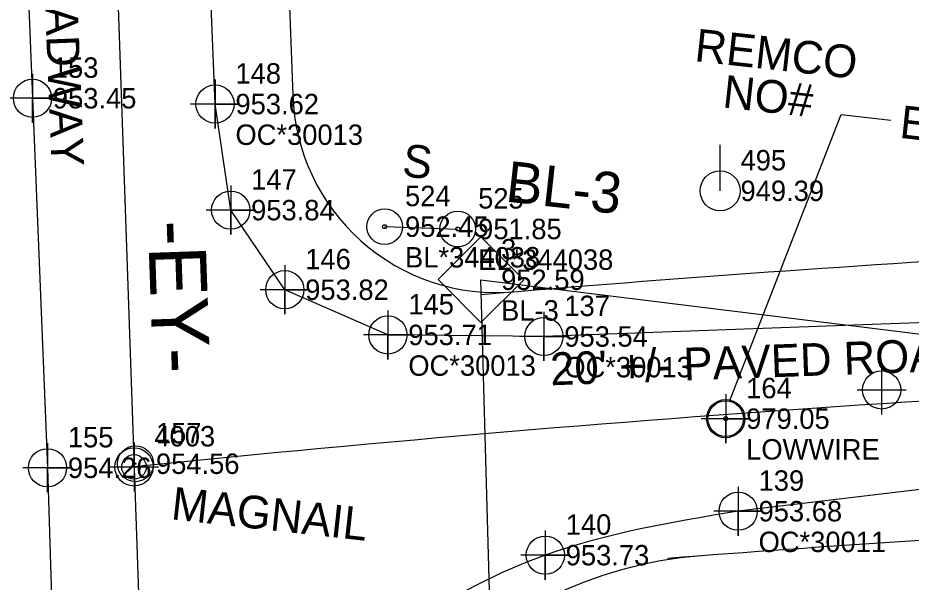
# Model space of a CAD drawing. Extents: x 1150279 to 1151282, y 655434 to 657999.
# Drawn here: x 1150558.1 to 1150667.5, y 657108.3 to 657177.3 of the extents above; entities that cross this region are included whole.
import ezdxf

# ---------------------------------------------------------------- set-up
doc = ezdxf.new("R2010")
doc.units = 0
for name, color, linetype in [('COGO Default Chain', 7, 'Continuous'), ('COGO Default Curve', 7, 'Continuous'), ('Cogo Default Point CELL', 7, 'Continuous'), ('COGO Default Point Number', 7, 'Continuous'), ('CTL Supplemental Horizontal and Vertical CELL', 7, 'Continuous'), ('CTL Supplemental Horizontal and Vertical Cogo Comment', 7, 'Continuous'), ('CTL Supplemental Horizontal and Vertical Cogo Elevation', 7, 'Continuous'), ('CTL Supplemental Horizontal and Vertical Cogo Number', 7, 'Continuous'), ('CTL Supplemental Horizontal and Vertical Text', 7, 'Continuous'), ('Default Symbol CELL', 7, 'Continuous'), ('Default Symbol Cogo Comment', 7, 'Continuous'), ('Default Symbol Cogo Elevation', 7, 'Continuous'), ('Default Symbol Cogo Number', 7, 'Continuous'), ('Exist Horizontal Alignment', 7, 'Continuous'), ('Exist Horizontal Alignment Direction Label', 7, 'Continuous'), ('Exist Horizontal Alignment Station Label', 7, 'Continuous'), ('Exist Other Culture Sign CELL', 7, 'Continuous'), ('Exist Other Culture Sign Cogo Comment', 7, 'Continuous'), ('Exist Other Culture Sign Cogo Elevation', 7, 'Continuous'), ('Exist Other Culture Sign Cogo Number', 7, 'Continuous'), ('Exist Other Culture Sign Text', 7, 'Continuous'), ('Exist Property Iron Pin CELL', 7, 'Continuous'), ('Exist Property Iron Pin Cogo Elevation', 7, 'Continuous'), ('Exist Property Iron Pin Cogo Number', 7, 'Continuous'), ('Exist Property Iron Pin Text', 7, 'Continuous'), ('Exist Right of Way Line', 7, 'Continuous'), ('Exist Roads EOP', 7, 'Continuous'), ('Exist Roads EOP Cogo Comment', 7, 'Continuous'), ('Exist Roads EOP Cogo Elevation', 7, 'Continuous'), ('Exist Roads EOP Cogo Number', 7, 'Continuous'), ('Exist Roads EOP Cogo Point CELL', 7, 'Continuous'), ('Exist Roads EOP Text', 7, 'Continuous'), ('Exist Utilities Other Located Object CELL', 7, 'Continuous'), ('Exist Utilities Other Located Object Leader', 7, 'Continuous'), ('Exist Utilities Other Located Object Text', 7, 'Continuous'), ('Exist Utilities Power Pole CELL', 7, 'Continuous'), ('Exist Utilities Power Pole Cogo Elevation', 7, 'Continuous'), ('Exist Utilities Power Pole Cogo Number', 7, 'Continuous'), ('Exist Utilities Power Pole Text', 7, 'Continuous'), ('Old_Level_4', 7, 'Continuous')]:
    doc.layers.add(name, color=color, linetype=linetype)

msp = doc.modelspace()

# ---------------------------------------------------------------- linework, layer by layer
at = {"layer": 'COGO Default Chain'}
for p, q in [((1150568.54, 657231.15), (1150575.96, 657017.52)), ((1150663.4, 655450.47), (1150614.76, 657145.26)), ((1150614.76, 657145.26), (1150931.29, 657106.06))]:
    msp.add_line(p, q, dxfattribs=at)
msp.add_arc((1150828.33, 654635.5), 2500, 91.66254, 95.87761, dxfattribs=at)
at = {"layer": 'COGO Default Curve'}
msp.add_arc((1150828.33, 654635.5), 2500, 91.66254, 95.87761, dxfattribs=at)
at = {"layer": 'Cogo Default Point CELL'}
for points in [[(1150663.84, 657134.78), (1150663.84, 657131.78)], [(1150660.84, 657131.78), (1150663.84, 657131.78)], [(1150663.84, 657131.78), (1150666.84, 657131.78)], [(1150663.84, 657131.78), (1150663.84, 657128.78)], [(1150572.32, 657125.36), (1150572.32, 657122.36)], [(1150572.32, 657125.36), (1150572.32, 657122.36)], [(1150569.32, 657122.36), (1150572.32, 657122.36)], [(1150569.32, 657122.36), (1150572.32, 657122.36)], [(1150572.32, 657122.36), (1150575.32, 657122.36)], [(1150572.32, 657122.36), (1150572.32, 657119.36)], [(1150572.32, 657122.36), (1150575.32, 657122.36)], [(1150572.32, 657122.36), (1150572.32, 657119.36)]]:
    msp.add_lwpolyline(points, dxfattribs=at)
for centre in [(1150663.84, 657131.78), (1150572.32, 657122.36), (1150572.32, 657122.36)]:
    msp.add_circle(centre, 2.34, dxfattribs=at)
at = {"layer": 'CTL Supplemental Horizontal and Vertical CELL'}
msp.add_line((1150614.76, 657145.26), (1150614.76, 657145.26), dxfattribs=at)
msp.add_lwpolyline([(1150609.54, 657145.28), (1150614.78, 657150.52), (1150620.03, 657145.27), (1150614.79, 657140.03)], close=True, dxfattribs=at)
at = {"layer": 'Default Symbol CELL'}
msp.add_lwpolyline([(1150644.76, 657131.26), (1150644.76, 657125.26), (1150644.76, 657128.26), (1150647.76, 657128.26), (1150641.76, 657128.26)], dxfattribs=at)
msp.add_circle((1150644.76, 657128.26), 2.34, dxfattribs=at)
at = {"layer": 'Exist Horizontal Alignment'}
msp.add_line((1150568.54, 657231.15), (1150575.96, 657017.52), dxfattribs=at)
msp.add_arc((1150828.33, 654635.5), 2500, 91.66254, 95.87761, dxfattribs=at)
at = {"layer": 'Exist Horizontal Alignment Station Label'}
msp.add_circle((1150572.32, 657122.36), 1.5, dxfattribs=at)
at = {"layer": 'Exist Other Culture Sign CELL'}
for centre, radius in [((1150603, 657151.76), 2.18), ((1150611.95, 657151.47), 2.18), ((1150603, 657151.76), 0.24), ((1150611.95, 657151.47), 0.24)]:
    msp.add_circle(centre, radius, dxfattribs=at)
at = {"layer": 'Exist Property Iron Pin CELL'}
for radius in [2.2, 0.0707]:
    msp.add_circle((1150572.51, 657122.75), radius, dxfattribs=at)
at = {"layer": 'Exist Right of Way Line'}
msp.add_line((1150589.52, 657231.88), (1150591.75, 657167.81), dxfattribs=at)
for centre, radius, start, end in [((1150616.74, 657168.68), 25, 181.9914, 274.7747), ((1150828.33, 654635.5), 2517, 91.66254, 94.86501), ((1150828.33, 654635.5), 2483, 91.66254, 94.40447), ((1150645.47, 657061.62), 50, 94.3102, 181.9914)]:
    msp.add_arc(centre, radius, start, end, dxfattribs=at)
at = {"layer": 'Exist Roads EOP'}
for p, q in [((1150582.24, 657166.76), (1150579.68, 657231.42)), ((1150622.5, 657138.32), (1150603.4, 657138.51))]:
    msp.add_line(p, q, dxfattribs=at)
for points in [[(1150555.6, 657230.84), (1150557.81, 657218.94), (1150559.89, 657167.47), (1150561.73, 657122.25), (1150563.33, 657070.95), (1150564.64, 657020.93), (1150563.6, 657016.73)], [(1150603.4, 657138.51), (1150590.78, 657144.04), (1150584.16, 657153.78), (1150582.24, 657166.76)], [(1150716.46, 657142.57), (1150671.62, 657140.1), (1150622.5, 657138.32)], [(1150717.08, 657124.05), (1150672.37, 657120.06), (1150646.28, 657116.94)]]:
    msp.add_lwpolyline(points, dxfattribs=at)
msp.add_spline([(1150646.28, 657116.94), (1150622.67, 657111.56), (1150606.22, 657102.96), (1150594, 657090.81), (1150585.84, 657066.56)], degree=3, dxfattribs=at)
at = {"layer": 'Exist Roads EOP Cogo Point CELL'}
for points in [[(1150559.89, 657170.47), (1150559.89, 657164.47), (1150559.89, 657167.47), (1150562.89, 657167.47), (1150556.89, 657167.47)], [(1150582.24, 657169.76), (1150582.24, 657163.76), (1150582.24, 657166.76), (1150585.24, 657166.76), (1150579.24, 657166.76)], [(1150584.16, 657156.78), (1150584.16, 657150.78), (1150584.16, 657153.78), (1150587.16, 657153.78), (1150581.16, 657153.78)], [(1150590.78, 657147.04), (1150590.78, 657141.04), (1150590.78, 657144.04), (1150593.78, 657144.04), (1150587.78, 657144.04)], [(1150603.4, 657141.51), (1150603.4, 657135.51), (1150603.4, 657138.51), (1150606.4, 657138.51), (1150600.4, 657138.51)], [(1150622.5, 657141.32), (1150622.5, 657135.32), (1150622.5, 657138.32), (1150625.5, 657138.32), (1150619.5, 657138.32)], [(1150561.73, 657125.25), (1150561.73, 657119.25), (1150561.73, 657122.25), (1150564.73, 657122.25), (1150558.73, 657122.25)], [(1150646.28, 657119.94), (1150646.28, 657113.94), (1150646.28, 657116.94), (1150649.28, 657116.94), (1150643.28, 657116.94)], [(1150622.67, 657114.56), (1150622.67, 657108.56), (1150622.67, 657111.56), (1150625.67, 657111.56), (1150619.67, 657111.56)]]:
    msp.add_lwpolyline(points, dxfattribs=at)
for centre in [(1150559.89, 657167.47), (1150582.24, 657166.76), (1150584.16, 657153.78), (1150590.78, 657144.04), (1150603.4, 657138.51), (1150622.5, 657138.32), (1150561.73, 657122.25), (1150646.28, 657116.94), (1150622.67, 657111.56)]:
    msp.add_circle(centre, 2.34, dxfattribs=at)
at = {"layer": 'Exist Utilities Other Located Object CELL'}
for radius in [2.18, 0.24]:
    msp.add_circle((1150644.76, 657128.26), radius, dxfattribs=at)
at = {"layer": 'Exist Utilities Other Located Object Leader'}
msp.add_lwpolyline([(1150645.27, 657130.5), (1150658.88, 657165.48), (1150664.98, 657164.8)], dxfattribs=at)
at = {"layer": 'Exist Utilities Power Pole CELL'}
for q in [(1150644.07, 657161.76), (1150644.07, 657156.14)]:
    msp.add_line((1150644.07, 657156.14), q, dxfattribs=at)
msp.add_circle((1150644.07, 657156.14), 2.45, dxfattribs=at)
at = {"layer": 'Old_Level_4'}
msp.add_line((1150603, 657151.76), (1150611.95, 657151.47), dxfattribs=at)

# ---------------------------------------------------------------- texts
at = {"layer": 'COGO Default Point Number'}
msp.add_text('4003', height=2.5, dxfattribs=at).set_placement((1150574.82, 657124.86))
at = {"layer": 'CTL Supplemental Horizontal and Vertical Cogo Comment'}
msp.add_text('BL-3', height=2.5, dxfattribs=at).set_placement((1150617.26, 657140.26))
at = {"layer": 'CTL Supplemental Horizontal and Vertical Cogo Elevation'}
msp.add_text('952.59', height=2.5, dxfattribs=at).set_placement((1150617.26, 657144.01))
at = {"layer": 'CTL Supplemental Horizontal and Vertical Cogo Number'}
msp.add_text('3', height=2.5, dxfattribs=at).set_placement((1150617.26, 657147.76))
at = {"layer": 'CTL Supplemental Horizontal and Vertical Text'}
msp.add_text('BL-3', height=5, rotation=353.6867, dxfattribs=at).set_placement((1150617.68, 657154.84))
at = {"layer": 'Default Symbol Cogo Comment'}
msp.add_text('LOWWIRE', height=2.5, dxfattribs=at).set_placement((1150647.26, 657123.26))
at = {"layer": 'Default Symbol Cogo Elevation'}
msp.add_text('979.05', height=2.5, dxfattribs=at).set_placement((1150647.26, 657127.01))
at = {"layer": 'Default Symbol Cogo Number'}
msp.add_text('164', height=2.5, dxfattribs=at).set_placement((1150647.26, 657130.76))
at = {"layer": 'Exist Horizontal Alignment Direction Label'}
msp.add_text('-EY-', height=7, rotation=271.9914, dxfattribs=at).set_placement((1150574.01, 657152.43))
at = {"layer": 'Exist Other Culture Sign Cogo Comment'}
for s, p in [('BL*344038', (1150605.5, 657146.76)), ('EL*344038', (1150614.45, 657146.47))]:
    msp.add_text(s, height=2.5, dxfattribs=at).set_placement(p)
at = {"layer": 'Exist Other Culture Sign Cogo Elevation'}
for s, p in [('952.45', (1150605.5, 657150.51)), ('951.85', (1150614.45, 657150.22))]:
    msp.add_text(s, height=2.5, dxfattribs=at).set_placement(p)
at = {"layer": 'Exist Other Culture Sign Cogo Number'}
for s, p in [('524', (1150605.5, 657154.26)), ('525', (1150614.45, 657153.97))]:
    msp.add_text(s, height=2.5, dxfattribs=at).set_placement(p)
at = {"layer": 'Exist Other Culture Sign Text'}
msp.add_text('S', height=4, rotation=353.6867, dxfattribs=at).set_placement((1150605.05, 657157.94))
at = {"layer": 'Exist Property Iron Pin Cogo Elevation'}
msp.add_text('954.56', height=2.5, dxfattribs=at).set_placement((1150575.01, 657121.5))
at = {"layer": 'Exist Property Iron Pin Cogo Number'}
msp.add_text('157', height=2.5, dxfattribs=at).set_placement((1150575.01, 657125.25))
at = {"layer": 'Exist Property Iron Pin Text'}
msp.add_text('MAGNAIL', height=4, rotation=353.6867, dxfattribs=at).set_placement((1150576.76, 657115.96))
at = {"layer": 'Exist Roads EOP Cogo Comment'}
for s, p in [('OC*30013', (1150584.74, 657161.76)), ('OC*30013', (1150605.9, 657133.51)), ('OC*30013', (1150625, 657133.32)), ('OC*30011', (1150648.78, 657111.94))]:
    msp.add_text(s, height=2.5, dxfattribs=at).set_placement(p)
at = {"layer": 'Exist Roads EOP Cogo Elevation'}
for s, p in [('953.45', (1150562.39, 657166.22)), ('953.62', (1150584.74, 657165.51)), ('953.84', (1150586.66, 657152.53)), ('953.82', (1150593.28, 657142.79)), ('953.71', (1150605.9, 657137.26)), ('953.54', (1150625, 657137.07)), ('954.26', (1150564.23, 657121)), ('953.68', (1150648.78, 657115.69)), ('953.73', (1150625.17, 657110.31))]:
    msp.add_text(s, height=2.5, dxfattribs=at).set_placement(p)
at = {"layer": 'Exist Roads EOP Cogo Number'}
for s, p in [('153', (1150562.39, 657169.97)), ('148', (1150584.74, 657169.26)), ('147', (1150586.66, 657156.28)), ('146', (1150593.28, 657146.54)), ('145', (1150605.9, 657141.01)), ('137', (1150625, 657140.82)), ('155', (1150564.23, 657124.75)), ('139', (1150648.78, 657119.44)), ('140', (1150625.17, 657114.06))]:
    msp.add_text(s, height=2.5, dxfattribs=at).set_placement(p)
at = {"layer": 'Exist Roads EOP Text'}
for s, rotation, p in [("22' PAVED ROADWAY", 272.3134, (1150559.98, 657214.72)), ("20' +/- PAVED ROADWAY", 2.0752, (1150623.33, 657132.34))]:
    msp.add_text(s, height=4, rotation=rotation, dxfattribs=at).set_placement(p)
at = {"layer": 'Exist Utilities Other Located Object Text'}
msp.add_text("ELEV = 979.05'", height=4, rotation=353.6867, dxfattribs=at).set_placement((1150665.93, 657162.64))
at = {"layer": 'Exist Utilities Power Pole Cogo Elevation'}
msp.add_text('949.39', height=2.5, dxfattribs=at).set_placement((1150646.57, 657154.89))
at = {"layer": 'Exist Utilities Power Pole Cogo Number'}
msp.add_text('495', height=2.5, dxfattribs=at).set_placement((1150646.57, 657158.64))
at = {"layer": 'Exist Utilities Power Pole Text'}
for s, p in [('REMCO', (1150640.84, 657172.02)), ('NO#', (1150644.27, 657166.36))]:
    msp.add_text(s, height=4, rotation=353.6867, dxfattribs=at).set_placement(p)

doc.saveas('drawing.dxf')
